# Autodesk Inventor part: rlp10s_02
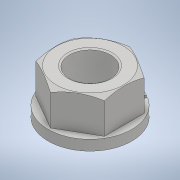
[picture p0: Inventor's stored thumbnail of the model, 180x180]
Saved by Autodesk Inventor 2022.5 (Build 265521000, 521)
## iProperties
Part Number: rlp10s_02
Material: 一般
Document SubType Name: Modeling
Designer: ImaoCorp
Density: 1 g/cm^3
Appearance: 既定
Author: ImaoCorp
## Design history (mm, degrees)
feature "rlp10s_02"
node "ソリッド1"
